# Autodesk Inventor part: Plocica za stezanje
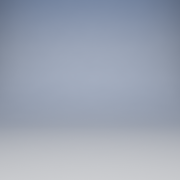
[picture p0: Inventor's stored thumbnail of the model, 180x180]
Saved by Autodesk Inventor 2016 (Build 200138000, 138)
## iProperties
Created: 2015-08
Part Number: Plocica za stezanje
Material: Generic
Document SubType Name: Modeling
Designer: stank
Density: 1 g/cm^3
Appearance: Default
Author: stank
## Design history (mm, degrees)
